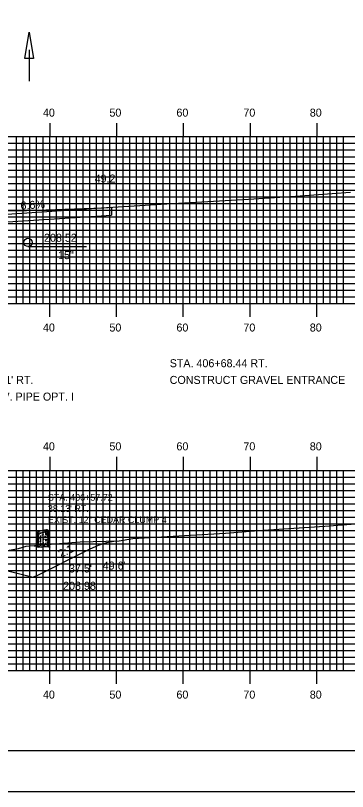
# Model space of a CAD drawing. Extents: x 852135 to 852479, y 364785 to 365005.
# Drawn here: x 852336.1 to 852385.8, y 364785.1 to 364901.4 of the extents above; entities that cross this region are included whole.
import ezdxf

# ---------------------------------------------------------------- set-up
doc = ezdxf.new("R2010")
doc.units = 0
for name, color, linetype in [('ANNOTATION', 7, 'Continuous'), ('BORDER', 7, 'Continuous'), ('D_Drainage_Culvert', 7, 'Continuous'), ('D_Drainage_Ditch_Line', 7, 'Continuous'), ('D_Roadway_FinishedGrade', 7, 'Continuous'), ('D_Roadway_Pavement', 7, 'Continuous'), ('D_Roadway_SlopeLines', 7, 'Continuous'), ('D_Roadway_SubGrade', 7, 'Continuous'), ('D_Text_Monospaced', 7, 'Continuous'), ('D_Text_Standard', 7, 'Continuous'), ('H_V ANNOTATION', 7, 'Continuous'), ('MAJOR', 7, 'Continuous'), ('MINOR', 7, 'Continuous'), ('PDRAIN', 7, 'Continuous'), ('PLOT BOUNDARY', 7, 'Continuous'), ('S_Roadway_Centerline', 7, 'Continuous'), ('S_Trees_Conifer_Pay', 7, 'Continuous')]:
    doc.layers.add(name, color=color, linetype=linetype)

msp = doc.modelspace()

# ---------------------------------------------------------------- linework, layer by layer
at = {"layer": 'BORDER'}
msp.add_lwpolyline([(852151.62, 364791.23), (852471.62, 364791.23), (852471.62, 365001.23), (852151.62, 365001.23)], close=True, dxfattribs=at)
at = {"layer": 'D_Drainage_Culvert'}
msp.add_circle((852337.95, 364867.38), 0.625, dxfattribs=at)
at = {"layer": 'D_Drainage_Ditch_Line'}
msp.add_line((852338.12, 364896.26), (852338.12, 364891.56), dxfattribs=at)
msp.add_lwpolyline([(852338.78, 364894.94), (852337.47, 364894.94), (852338.12, 364898.88)], close=True, dxfattribs=at)
at = {"layer": 'D_Roadway_FinishedGrade'}
msp.add_lwpolyline([(852321.22, 364870.94), (852327.22, 364871.12), (852333.22, 364871.54), (852350.45, 364872.65)], dxfattribs=at)
at = {"layer": 'D_Roadway_Pavement'}
msp.add_line((852339.1, 364817.4), (852338.73, 364817.21), dxfattribs=at)
msp.add_lwpolyline([(852301.22, 364822.38), (852321.23, 364821.58), (852338.73, 364817.21)], dxfattribs=at)
at = {"layer": 'D_Roadway_SlopeLines'}
msp.add_lwpolyline([(852339.1, 364817.4), (852347.26, 364821.47), (852348.51, 364822.02), (852349.76, 364822.42), (852350.81, 364822.63)], dxfattribs=at)
at = {"layer": 'D_Roadway_SubGrade'}
msp.add_line((852350.45, 364872.65), (852350.45, 364871.48), dxfattribs=at)
msp.add_lwpolyline([(852330.29, 364870.17), (852333.3, 364870.38), (852350.45, 364871.48)], dxfattribs=at)
at = {"layer": 'MAJOR'}
for p, q in [((852341.22, 364885.24), (852341.22, 364883.23)), ((852351.22, 364885.24), (852351.22, 364883.23)), ((852361.22, 364885.24), (852361.22, 364883.23)), ((852371.22, 364885.24), (852371.22, 364883.23)), ((852381.22, 364885.24), (852381.22, 364883.23)), ((852301.22, 364883.23), (852441.22, 364883.23)), ((852301.22, 364883.23), (852441.22, 364883.23)), ((852341.22, 364858.23), (852341.22, 364883.23)), ((852351.22, 364858.23), (852351.22, 364883.23)), ((852361.22, 364858.23), (852361.22, 364883.23)), ((852371.22, 364858.23), (852371.22, 364883.23)), ((852381.22, 364858.23), (852381.22, 364883.23)), ((852301.22, 364878.23), (852441.22, 364878.23)), ((852301.22, 364873.23), (852441.22, 364873.23)), ((852301.22, 364868.23), (852441.22, 364868.23)), ((852301.22, 364863.23), (852441.22, 364863.23)), ((852301.22, 364858.23), (852441.22, 364858.23)), ((852301.22, 364858.23), (852441.22, 364858.23)), ((852341.22, 364856.23), (852341.22, 364858.23)), ((852351.22, 364856.23), (852351.22, 364858.23)), ((852361.22, 364856.23), (852361.22, 364858.23)), ((852371.22, 364856.23), (852371.22, 364858.23)), ((852381.22, 364856.23), (852381.22, 364858.23)), ((852341.22, 364835.24), (852341.22, 364833.23)), ((852351.22, 364835.24), (852351.22, 364833.23)), ((852361.22, 364835.24), (852361.22, 364833.23)), ((852371.22, 364835.24), (852371.22, 364833.23)), ((852381.22, 364835.24), (852381.22, 364833.23)), ((852161.22, 364833.23), (852441.22, 364833.23)), ((852161.22, 364833.23), (852441.22, 364833.23)), ((852341.22, 364803.23), (852341.22, 364833.23)), ((852351.22, 364803.23), (852351.22, 364833.23)), ((852361.22, 364803.23), (852361.22, 364833.23)), ((852371.22, 364803.23), (852371.22, 364833.23)), ((852381.22, 364803.23), (852381.22, 364833.23)), ((852161.22, 364828.23), (852441.22, 364828.23)), ((852161.22, 364823.23), (852441.22, 364823.23)), ((852161.22, 364818.23), (852441.22, 364818.23)), ((852161.22, 364813.23), (852441.22, 364813.23)), ((852161.22, 364808.23), (852441.22, 364808.23)), ((852161.22, 364803.23), (852441.22, 364803.23)), ((852161.22, 364803.23), (852441.22, 364803.23)), ((852341.22, 364801.23), (852341.22, 364803.23)), ((852351.22, 364801.23), (852351.22, 364803.23)), ((852361.22, 364801.23), (852361.22, 364803.23)), ((852371.22, 364801.23), (852371.22, 364803.23)), ((852381.22, 364801.23), (852381.22, 364803.23))]:
    msp.add_line(p, q, dxfattribs=at)
at = {"layer": 'MINOR'}
for p, q in [((852336.22, 364858.23), (852336.22, 364883.23)), ((852337.22, 364858.23), (852337.22, 364883.23)), ((852338.22, 364858.23), (852338.22, 364883.23)), ((852339.22, 364858.23), (852339.22, 364883.23)), ((852340.22, 364858.23), (852340.22, 364883.23)), ((852342.22, 364858.23), (852342.22, 364883.23)), ((852343.22, 364858.23), (852343.22, 364883.23)), ((852344.22, 364858.23), (852344.22, 364883.23)), ((852345.22, 364858.23), (852345.22, 364883.23)), ((852346.22, 364858.23), (852346.22, 364883.23)), ((852347.22, 364858.23), (852347.22, 364883.23)), ((852348.22, 364858.23), (852348.22, 364883.23)), ((852349.22, 364858.23), (852349.22, 364883.23)), ((852350.22, 364858.23), (852350.22, 364883.23)), ((852352.22, 364858.23), (852352.22, 364883.23)), ((852353.22, 364858.23), (852353.22, 364883.23)), ((852354.22, 364858.23), (852354.22, 364883.23)), ((852355.22, 364858.23), (852355.22, 364883.23)), ((852356.22, 364858.23), (852356.22, 364883.23)), ((852357.22, 364858.23), (852357.22, 364883.23)), ((852358.22, 364858.23), (852358.22, 364883.23)), ((852359.22, 364858.23), (852359.22, 364883.23)), ((852360.22, 364858.23), (852360.22, 364883.23)), ((852362.22, 364858.23), (852362.22, 364883.23)), ((852363.22, 364858.23), (852363.22, 364883.23)), ((852364.22, 364858.23), (852364.22, 364883.23)), ((852365.22, 364858.23), (852365.22, 364883.23)), ((852366.22, 364858.23), (852366.22, 364883.23)), ((852367.22, 364858.23), (852367.22, 364883.23)), ((852368.22, 364858.23), (852368.22, 364883.23)), ((852369.22, 364858.23), (852369.22, 364883.23)), ((852370.22, 364858.23), (852370.22, 364883.23)), ((852372.22, 364858.23), (852372.22, 364883.23)), ((852373.22, 364858.23), (852373.22, 364883.23)), ((852374.22, 364858.23), (852374.22, 364883.23)), ((852375.22, 364858.23), (852375.22, 364883.23)), ((852376.22, 364858.23), (852376.22, 364883.23)), ((852377.22, 364858.23), (852377.22, 364883.23)), ((852378.22, 364858.23), (852378.22, 364883.23)), ((852379.22, 364858.23), (852379.22, 364883.23)), ((852380.22, 364858.23), (852380.22, 364883.23)), ((852382.22, 364858.23), (852382.22, 364883.23)), ((852383.22, 364858.23), (852383.22, 364883.23)), ((852384.22, 364858.23), (852384.22, 364883.23)), ((852385.22, 364858.23), (852385.22, 364883.23)), ((852301.22, 364882.23), (852441.22, 364882.23)), ((852301.22, 364881.23), (852441.22, 364881.23)), ((852301.22, 364880.23), (852441.22, 364880.23)), ((852301.22, 364879.23), (852441.22, 364879.23)), ((852301.22, 364877.23), (852441.22, 364877.23)), ((852301.22, 364876.23), (852441.22, 364876.23)), ((852301.22, 364875.23), (852441.22, 364875.23)), ((852301.22, 364874.23), (852441.22, 364874.23)), ((852301.22, 364872.23), (852441.22, 364872.23)), ((852301.22, 364871.23), (852441.22, 364871.23)), ((852301.22, 364870.23), (852441.22, 364870.23)), ((852301.22, 364869.23), (852441.22, 364869.23)), ((852301.22, 364867.23), (852441.22, 364867.23)), ((852301.22, 364866.23), (852441.22, 364866.23)), ((852301.22, 364865.23), (852441.22, 364865.23)), ((852301.22, 364864.23), (852441.22, 364864.23)), ((852301.22, 364862.23), (852441.22, 364862.23)), ((852301.22, 364861.23), (852441.22, 364861.23)), ((852301.22, 364860.23), (852441.22, 364860.23)), ((852301.22, 364859.23), (852441.22, 364859.23)), ((852336.22, 364803.23), (852336.22, 364833.23)), ((852337.22, 364803.23), (852337.22, 364833.23)), ((852338.22, 364803.23), (852338.22, 364833.23)), ((852339.22, 364803.23), (852339.22, 364833.23)), ((852340.22, 364803.23), (852340.22, 364833.23)), ((852342.22, 364803.23), (852342.22, 364833.23)), ((852343.22, 364803.23), (852343.22, 364833.23)), ((852344.22, 364803.23), (852344.22, 364833.23)), ((852345.22, 364803.23), (852345.22, 364833.23)), ((852346.22, 364803.23), (852346.22, 364833.23)), ((852347.22, 364803.23), (852347.22, 364833.23)), ((852348.22, 364803.23), (852348.22, 364833.23)), ((852349.22, 364803.23), (852349.22, 364833.23)), ((852350.22, 364803.23), (852350.22, 364833.23)), ((852352.22, 364803.23), (852352.22, 364833.23)), ((852353.22, 364803.23), (852353.22, 364833.23)), ((852354.22, 364803.23), (852354.22, 364833.23)), ((852355.22, 364803.23), (852355.22, 364833.23)), ((852356.22, 364803.23), (852356.22, 364833.23)), ((852357.22, 364803.23), (852357.22, 364833.23)), ((852358.22, 364803.23), (852358.22, 364833.23)), ((852359.22, 364803.23), (852359.22, 364833.23)), ((852360.22, 364803.23), (852360.22, 364833.23)), ((852362.22, 364803.23), (852362.22, 364833.23)), ((852363.22, 364803.23), (852363.22, 364833.23)), ((852364.22, 364803.23), (852364.22, 364833.23)), ((852365.22, 364803.23), (852365.22, 364833.23)), ((852366.22, 364803.23), (852366.22, 364833.23)), ((852367.22, 364803.23), (852367.22, 364833.23)), ((852368.22, 364803.23), (852368.22, 364833.23)), ((852369.22, 364803.23), (852369.22, 364833.23)), ((852370.22, 364803.23), (852370.22, 364833.23)), ((852372.22, 364803.23), (852372.22, 364833.23)), ((852373.22, 364803.23), (852373.22, 364833.23)), ((852374.22, 364803.23), (852374.22, 364833.23)), ((852375.22, 364803.23), (852375.22, 364833.23)), ((852376.22, 364803.23), (852376.22, 364833.23)), ((852377.22, 364803.23), (852377.22, 364833.23)), ((852378.22, 364803.23), (852378.22, 364833.23)), ((852379.22, 364803.23), (852379.22, 364833.23)), ((852380.22, 364803.23), (852380.22, 364833.23)), ((852382.22, 364803.23), (852382.22, 364833.23)), ((852383.22, 364803.23), (852383.22, 364833.23)), ((852384.22, 364803.23), (852384.22, 364833.23)), ((852385.22, 364803.23), (852385.22, 364833.23)), ((852161.22, 364832.23), (852441.22, 364832.23)), ((852161.22, 364831.23), (852441.22, 364831.23)), ((852161.22, 364830.23), (852441.22, 364830.23)), ((852161.22, 364829.23), (852441.22, 364829.23)), ((852161.22, 364827.23), (852441.22, 364827.23)), ((852161.22, 364826.23), (852441.22, 364826.23)), ((852161.22, 364825.23), (852441.22, 364825.23)), ((852161.22, 364824.23), (852441.22, 364824.23)), ((852161.22, 364822.23), (852441.22, 364822.23)), ((852161.22, 364821.23), (852441.22, 364821.23)), ((852161.22, 364820.23), (852441.22, 364820.23)), ((852161.22, 364819.23), (852441.22, 364819.23)), ((852161.22, 364817.23), (852441.22, 364817.23)), ((852161.22, 364816.23), (852441.22, 364816.23)), ((852161.22, 364815.23), (852441.22, 364815.23)), ((852161.22, 364814.23), (852441.22, 364814.23)), ((852161.22, 364812.23), (852441.22, 364812.23)), ((852161.22, 364811.23), (852441.22, 364811.23)), ((852161.22, 364810.23), (852441.22, 364810.23)), ((852161.22, 364809.23), (852441.22, 364809.23)), ((852161.22, 364807.23), (852441.22, 364807.23)), ((852161.22, 364806.23), (852441.22, 364806.23)), ((852161.22, 364805.23), (852441.22, 364805.23)), ((852161.22, 364804.23), (852441.22, 364804.23))]:
    msp.add_line(p, q, dxfattribs=at)
at = {"layer": 'PDRAIN'}
for p, q in [((852337.95, 364866.76), (852346.72, 364866.76)), ((852338.73, 364817.21), (852349.5, 364817.21))]:
    msp.add_line(p, q, dxfattribs=at)
at = {"layer": 'PLOT BOUNDARY'}
msp.add_lwpolyline([(852135.43, 364785.11), (852475.43, 364785.11), (852475.43, 365005.11), (852135.43, 365005.11)], close=True, dxfattribs=at)
at = {"layer": 'S_Roadway_Centerline'}
for points in [[(852301.22, 364871.51), (852302.52, 364871.56), (852311.73, 364871.9), (852312.88, 364871.81), (852313.01, 364871.82), (852315.56, 364871.99), (852319.29, 364872.03), (852319.36, 364872.02), (852320.78, 364871.98), (852320.81, 364871.97), (852322.94, 364871.68), (852325.43, 364871.73), (852328.13, 364871.81), (852332.4, 364872.03), (852334.7, 364872.14), (852337.73, 364872.18), (852347.79, 364872.52), (852349.29, 364872.58), (852350.66, 364872.66), (852357.9, 364873.1), (852371.01, 364873.85), (852378.05, 364874.33), (852386.25, 364874.92)], [(852331.73, 364820.66), (852336.51, 364821.53), (852337.68, 364821.86), (852345.77, 364822.54), (852351.61, 364822.65), (852353.68, 364823.04), (852361.39, 364823.47), (852367.53, 364823.84), (852372.46, 364824.21), (852380.09, 364824.72), (852382.41, 364824.87), (852391.59, 364825.55)]]:
    msp.add_lwpolyline(points, dxfattribs=at)
at = {"layer": 'S_Trees_Conifer_Pay'}
for p, q in [((852340.94, 364824.17), (852340.94, 364824.01)), ((852341.01, 364822.6), (852341.01, 364824.25)), ((852339.35, 364822.19), (852339.35, 364823.91)), ((852339.39, 364823.87), (852339.39, 364823.4)), ((852339.39, 364823.34), (852339.39, 364823.03)), ((852339.39, 364822.98), (852339.39, 364822.49)), ((852339.45, 364823.86), (852339.45, 364823.76)), ((852339.45, 364823.69), (852339.45, 364823.49)), ((852339.45, 364823.43), (852339.45, 364823.23)), ((852339.45, 364823.18), (852339.45, 364822.84)), ((852339.58, 364823.85), (852339.58, 364823.62)), ((852339.58, 364823.58), (852339.58, 364823.51)), ((852339.58, 364823.1), (852339.58, 364822.96)), ((852339.8, 364823.87), (852339.8, 364823.71)), ((852339.8, 364823.47), (852339.8, 364823.23)), ((852339.8, 364822.99), (852339.8, 364822.84)), ((852340.2, 364823.64), (852340.2, 364823.55)), ((852340.2, 364823.03), (852340.2, 364822.95)), ((852340.59, 364823.92), (852340.59, 364823.72)), ((852340.59, 364823.66), (852340.59, 364823.57)), ((852340.59, 364823.22), (852340.59, 364823.12)), ((852340.82, 364824.11), (852340.82, 364823.89)), ((852340.82, 364823.8), (852340.82, 364823.75)), ((852340.82, 364823.42), (852340.82, 364823.29)), ((852340.82, 364823.17), (852340.82, 364823.07)), ((852340.88, 364823.62), (852340.83, 364823.56)), ((852340.94, 364823.94), (852340.94, 364823.81)), ((852340.94, 364823.63), (852340.94, 364823.29)), ((852340.94, 364823.25), (852340.94, 364823.09)), ((852340.94, 364823.04), (852340.94, 364822.83)), ((852339.39, 364822.44), (852339.39, 364822.19)), ((852339.45, 364822.79), (852339.45, 364822.66)), ((852339.45, 364822.56), (852339.45, 364822.18)), ((852339.58, 364822.69), (852339.58, 364822.55)), ((852339.58, 364822.29), (852339.58, 364822.19)), ((852339.58, 364821.79), (852339.74, 364821.86)), ((852339.8, 364822.79), (852339.8, 364822.62)), ((852339.8, 364822.34), (852339.8, 364822.19)), ((852340.2, 364822.93), (852340.2, 364822.78)), ((852340.2, 364822.49), (852340.2, 364822.34)), ((852340.59, 364822.75), (852340.59, 364822.6)), ((852340.59, 364822.37), (852340.59, 364822.28)), ((852340.82, 364822.93), (852340.82, 364822.79)), ((852340.82, 364822.56), (852340.82, 364822.39)), ((852340.94, 364822.8), (852340.94, 364822.72)), ((852340.94, 364822.68), (852340.94, 364822.51)), ((852340.01, 364821.73), (852339.89, 364821.79))]:
    msp.add_line(p, q, dxfattribs=at)
for points in [[(852339.53, 364823.22), (852339.52, 364823.31), (852339.56, 364823.29), (852339.56, 364823.19)], [(852340.79, 364823.71), (852340.76, 364823.62), (852340.76, 364823.55), (852340.79, 364823.49)], [(852340.83, 364823.74), (852340.86, 364823.67), (852340.91, 364823.73), (852340.97, 364823.79), (852341.06, 364823.99), (852341.13, 364824.04), (852341.16, 364824.04)], [(852340.84, 364823.49), (852340.88, 364823.62), (852340.94, 364823.73), (852340.97, 364823.8), (852341.04, 364823.95)], [(852341.06, 364823.98), (852341.13, 364823.98), (852341.2, 364823.88)], [(852341.01, 364822.6), (852341.06, 364822.34), (852341.08, 364822.06), (852341.14, 364821.94), (852341.27, 364821.91), (852341.04, 364821.87), (852341.04, 364821.87), (852341.05, 364821.82), (852341.29, 364821.73), (852341.02, 364821.74), (852340.66, 364821.76), (852340.34, 364821.75), (852340.35, 364821.84), (852340.2, 364821.75), (852340.01, 364821.73), (852340.04, 364821.66), (852339.77, 364821.71), (852339.55, 364821.68), (852339.26, 364821.7), (852339.55, 364821.75), (852339.58, 364821.79), (852339.41, 364821.85), (852339.18, 364821.86), (852338.94, 364821.86), (852339.28, 364821.92), (852339.32, 364822), (852339.35, 364822.19)], [(852339.39, 364822.14), (852339.37, 364822.06), (852339.35, 364821.97)], [(852339.47, 364822.12), (852339.48, 364822), (852339.43, 364821.92), (852339.41, 364821.85)], [(852339.64, 364822.15), (852339.64, 364822.02), (852339.55, 364821.92)], [(852339.86, 364821.91), (852339.93, 364822), (852339.96, 364822.14)], [(852340.35, 364821.84), (852340.42, 364821.98), (852340.43, 364822.08)], [(852340.6, 364822.21), (852340.61, 364822.08), (852340.69, 364822.04)], [(852340.66, 364822.82), (852340.68, 364822.74), (852340.72, 364822.75), (852340.71, 364822.92)], [(852340.88, 364821.82), (852340.86, 364821.95), (852340.79, 364822.08)], [(852340.84, 364822.31), (852340.91, 364822.21), (852340.92, 364822.03), (852341.04, 364821.87)], [(852340.94, 364822.46), (852340.94, 364822.31), (852340.99, 364822.24), (852341, 364822.04)]]:
    msp.add_lwpolyline(points, dxfattribs=at)
for centre, radius, start, end in [((852341.2, 364819.14), 5.18, 101.7194, 108.0594), ((852341.2, 364819.14), 5.18, 95.3794, 101.7194), ((852340.79, 364823.5), 0.802, 79.2194, 95.3794), ((852340.51, 364824.85), 0.802, 288.0594, 304.2194), ((852340.9, 364824.04), 0.251, 71.0501, 79.2194), ((852340.82, 364824.4), 0.251, 304.2194, 312.3887), ((852340.95, 364824.2), 0.0817, 56.7194, 71.0501), ((852340.97, 364824.23), 0.0527, 46.923, 56.7194), ((852340.94, 364824.27), 0.0817, 312.3887, 326.7194), ((852340.98, 364824.24), 0.0314, 34.2194, 46.923), ((852340.96, 364824.25), 0.0527, 326.7194, 336.5158), ((852340.98, 364824.24), 0.0264, 23.4074, 34.2194), ((852340.99, 364824.25), 0.0226, 11.7194, 23.4074), ((852340.98, 364824.25), 0.0264, 349.2194, 0.0315), ((852340.99, 364824.25), 0.0226, 0.0315, 11.7194), ((852340.98, 364824.25), 0.0314, 336.5158, 349.2194), ((852339.42, 364823.88), 0.0817, 132.3887, 146.7194), ((852339.4, 364823.9), 0.0527, 146.7194, 156.5158), ((852339.38, 364823.91), 0.0314, 156.5158, 169.2194), ((852339.37, 364823.91), 0.0264, 169.2194, 180.0315), ((852339.37, 364823.91), 0.0226, 180.0315, 191.7194), ((852339.37, 364823.91), 0.0226, 191.7194, 203.4074), ((852339.37, 364823.91), 0.0264, 203.4074, 214.2194), ((852339.38, 364823.91), 0.0314, 214.2194, 226.923), ((852339.38, 364823.73), 0.0334, 163.9485, 180), ((852339.38, 364823.73), 0.0334, 180, 196.0515), ((852339.39, 364823.73), 0.0441, 196.0515, 210), ((852339.4, 364823.74), 0.0624, 210, 228.7494), ((852339.38, 364823.28), 0.0334, 163.9485, 180), ((852339.38, 364823.28), 0.0334, 180, 196.0515), ((852339.39, 364823.29), 0.0441, 196.0515, 210), ((852339.4, 364823.3), 0.0624, 210, 228.7494), ((852339.38, 364823.07), 0.0334, 163.9485, 180), ((852339.38, 364823.07), 0.0334, 180, 196.0515), ((852339.39, 364823.08), 0.0441, 196.0515, 210), ((852339.4, 364823.09), 0.0624, 210, 228.7494), ((852339.39, 364823.93), 0.0527, 226.923, 236.7194), ((852339.41, 364823.95), 0.0817, 236.7194, 251.0501), ((852339.48, 364823.83), 0.172, 228.7494, 240), ((852339.48, 364823.38), 0.172, 228.7494, 240), ((852339.48, 364823.17), 0.172, 228.7494, 240), ((852339.54, 364823.76), 0.251, 124.2194, 132.3887), ((852339.46, 364824.11), 0.251, 251.0501, 259.2194), ((852339.85, 364823.3), 0.802, 108.0594, 124.2194), ((852339.68, 364824.17), 0.571, 240, 240.3367), ((852339.68, 364823.96), 0.571, 240, 247.0587), ((852339.68, 364823.72), 0.571, 240, 240.3367), ((852339.68, 364823.51), 0.571, 240, 246.8597), ((852339.57, 364824.65), 0.802, 259.2194, 275.3794), ((852339.68, 364824.17), 0.571, 246.8597, 257.9846), ((852339.16, 364829.01), 5.18, 275.3794, 281.7194), ((852340.18, 364827.24), 4.12, 264.081, 266.6676), ((852340.18, 364827.92), 4.12, 264.6955, 266.7331), ((852340.18, 364827.69), 4.12, 268.0751, 270), ((852340.18, 364827.69), 4.12, 270, 270.3581), ((852339.16, 364829.01), 5.18, 281.7194, 288.0594), ((852340.18, 364827.48), 4.12, 273.7052, 275.9504), ((852340.18, 364827.69), 4.12, 275.7849, 277.0558), ((852340.18, 364827.92), 4.12, 276.238, 278.1032), ((852340.18, 364827.24), 4.12, 277.6125, 278.1032), ((852340.68, 364824.4), 0.571, 278.1032, 284.3667), ((852340.68, 364823.72), 0.571, 278.1032, 286.9296), ((852340.68, 364824.56), 0.571, 284.4317, 292.4132), ((852340.68, 364823.96), 0.571, 284.4493, 297.0429), ((852340.68, 364824.4), 0.571, 297.0237, 300), ((852340.68, 364823.72), 0.571, 297.1896, 300), ((852340.68, 364823.51), 0.571, 297.1896, 300), ((852340.88, 364823.38), 0.172, 300, 311.2506), ((852340.88, 364823.17), 0.172, 300, 311.2506), ((852340.88, 364824.21), 0.172, 300, 311.2506), ((852340.88, 364824.06), 0.172, 300, 311.2506), ((852340.95, 364824.13), 0.0624, 311.2506, 330), ((852340.95, 364823.98), 0.0624, 311.2506, 330), ((852340.95, 364823.3), 0.0624, 311.2506, 330), ((852340.95, 364823.09), 0.0624, 311.2506, 330), ((852340.97, 364823.29), 0.0441, 330, 343.9485), ((852340.97, 364823.08), 0.0441, 330, 343.9485), ((852340.98, 364824.12), 0.0334, 343.9485, 354.2151), ((852340.97, 364824.12), 0.0441, 330, 343.9485), ((852340.97, 364823.97), 0.0441, 330, 343.9485), ((852340.98, 364823.96), 0.0334, 343.9485, 354.2151), ((852340.98, 364823.52), 0.0334, 343.9485, 354.2151), ((852340.98, 364823.28), 0.0334, 343.9485, 354.2151), ((852340.98, 364823.07), 0.0334, 343.9485, 354.2151), ((852339.38, 364822.84), 0.0334, 163.9485, 180), ((852339.38, 364822.84), 0.0334, 180, 196.0515), ((852339.39, 364822.84), 0.0441, 196.0515, 210), ((852339.4, 364822.85), 0.0624, 210, 228.7494), ((852339.38, 364822.64), 0.0334, 163.9485, 180), ((852339.38, 364822.44), 0.0334, 163.9485, 180), ((852339.38, 364822.44), 0.0334, 180, 196.0515), ((852339.39, 364822.45), 0.0441, 196.0515, 210), ((852339.4, 364822.46), 0.0624, 210, 228.7494), ((852339.38, 364822.22), 0.0334, 163.9485, 180), ((852339.38, 364822.22), 0.0334, 180, 196.0515), ((852339.39, 364822.23), 0.0441, 196.0515, 210), ((852339.4, 364822.24), 0.0624, 210, 228.7494), ((852339.48, 364822.93), 0.172, 228.7494, 240), ((852339.48, 364822.54), 0.172, 228.7494, 240), ((852339.48, 364822.32), 0.172, 228.7494, 240), ((852339.68, 364823.28), 0.571, 240, 246.8597), ((852339.67, 364823.09), 0.571, 241.2369, 248.0268), ((852339.68, 364822.88), 0.571, 240, 246.8597), ((852339.68, 364822.66), 0.571, 240, 244.5314), ((852339.68, 364823.51), 0.571, 259.2707, 261.8968), ((852340.18, 364827.03), 4.12, 261.8968, 263.1474), ((852340.18, 364826.18), 4.12, 262.4438, 263.512), ((852340.18, 364826.6), 4.12, 263.4991, 265.8397), ((852340.18, 364826.8), 4.12, 264.716, 266.3193), ((852340.18, 364826.4), 4.12, 267.8117, 270), ((852340.18, 364827.03), 4.12, 270, 270.3581), ((852340.18, 364826.4), 4.12, 270, 270.1328), ((852340.18, 364827.03), 4.12, 273.1493, 275.4569), ((852340.18, 364826.4), 4.12, 275.7849, 276.7896), ((852340.18, 364826.18), 4.12, 277.3684, 278.1032), ((852340.68, 364822.66), 0.571, 278.1032, 281.637), ((852340.68, 364823.28), 0.571, 285.3983, 297.1896), ((852340.68, 364822.88), 0.571, 288.5067, 297.2721), ((852340.68, 364823.08), 0.571, 289.2907, 300), ((852340.88, 364822.74), 0.172, 300, 311.2506), ((852340.88, 364822.32), 0.172, 300, 311.2506), ((852340.95, 364822.65), 0.0624, 311.2506, 330), ((852340.95, 364822.24), 0.0624, 311.2506, 330), ((852340.97, 364822.64), 0.0441, 330, 343.9485), ((852340.97, 364822.23), 0.0441, 330, 343.9485), ((852340.98, 364822.64), 0.0334, 343.9485, 354.2151), ((852340.98, 364822.22), 0.0334, 343.9485, 354.2151)]:
    msp.add_arc(centre, radius, start, end, dxfattribs=at)

# ---------------------------------------------------------------- texts
at = {"layer": 'ANNOTATION'}
for s, rotation, p in [('6.6%', 3.769, (852336.86, 364872.29)), ('2:1', 26.5651, (852342.86, 364820.09))]:
    msp.add_text(s, height=1.2, rotation=rotation, dxfattribs=at).set_placement(p)
for s, p in [('208.52', (852340.35, 364867.48)), ('15"', (852342.46, 364864.88)), ("37.5'", (852344.09, 364817.93)), ('208.98', (852343.21, 364815.33))]:
    msp.add_text(s, height=1.2, dxfattribs=at).set_placement(p)
at = {"layer": 'D_Text_Monospaced'}
for s, p in [('STA. 406+57.72', (852340.93, 364828.68)), ("38.13' RT.", (852340.93, 364827.01)), ('EXIST. 12" CEDAR CLUMP 4', (852340.93, 364825.33))]:
    msp.add_text(s, height=1, dxfattribs=at).set_placement(p)
at = {"layer": 'D_Text_Standard'}
for s, p in [("49.2'", (852347.93, 364876.35)), ('STA. 406+68.44 RT.', (852359.18, 364848.68)), ("TO STA. 406+91.04, 37.1' RT.", (852317.1, 364846.18)), ('CONSTRUCT GRAVEL ENTRANCE', (852359.18, 364846.18)), ('INSTALL 15" X 40\' CULV. PIPE OPT. I', (852317.1, 364843.68)), ("49.6'", (852349.15, 364818.36))]:
    msp.add_text(s, height=1.2, dxfattribs=at).set_placement(p)
at = {"layer": 'H_V ANNOTATION'}
for s, p in [('40', (852340.19, 364886.23)), ('50', (852350.15, 364886.23)), ('60', (852360.19, 364886.23)), ('70', (852370.22, 364886.23)), ('80', (852380.17, 364886.23)), ('40', (852340.19, 364854.03)), ('50', (852350.15, 364854.03)), ('60', (852360.19, 364854.03)), ('70', (852370.22, 364854.03)), ('80', (852380.17, 364854.03)), ('40', (852340.19, 364836.23)), ('50', (852350.15, 364836.23)), ('60', (852360.19, 364836.23)), ('70', (852370.22, 364836.23)), ('80', (852380.17, 364836.23)), ('40', (852340.19, 364799.03)), ('50', (852350.15, 364799.03)), ('60', (852360.19, 364799.03)), ('70', (852370.22, 364799.03)), ('80', (852380.17, 364799.03))]:
    msp.add_text(s, height=1.2, dxfattribs=at).set_placement(p)

doc.saveas('drawing.dxf')
